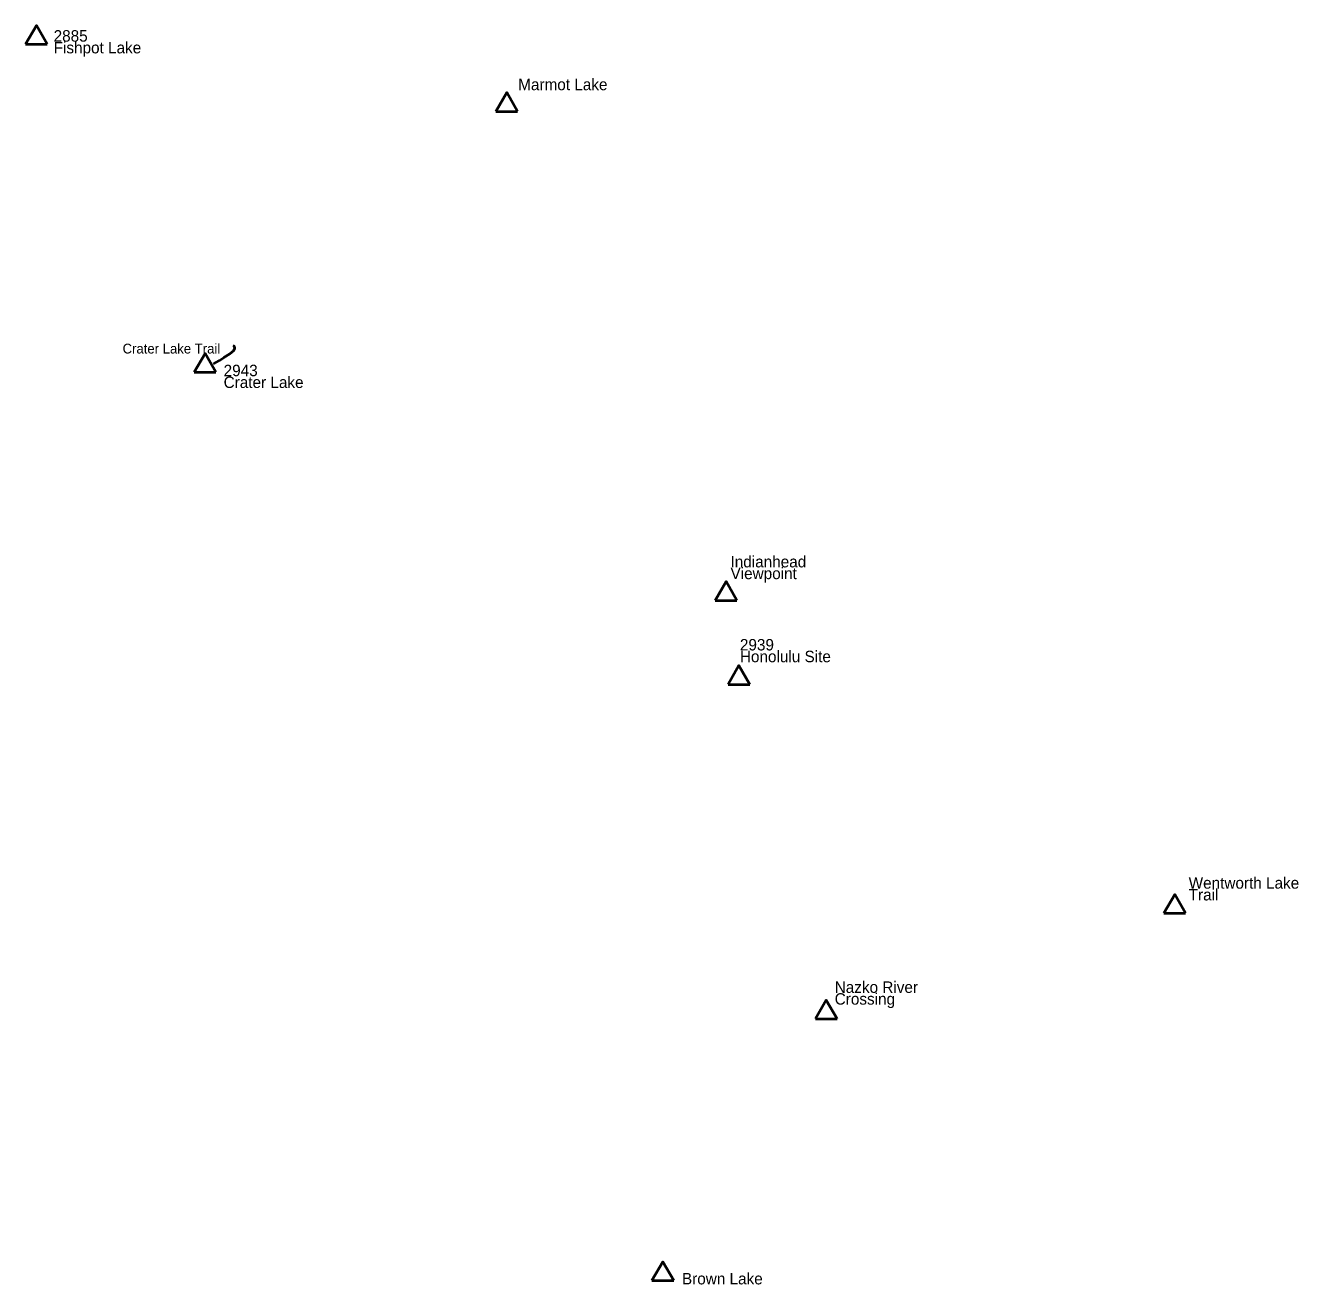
# Model space of a CAD drawing. Extents: x 322505 to 642419, y 5806860 to 5919753.
# Drawn here: x 446984 to 485932, y 5828406 to 5866932 of the extents above; entities that cross this region are included whole.
import ezdxf

# ---------------------------------------------------------------- set-up
doc = ezdxf.new("R2010")
doc.units = 0
doc.header["$LTSCALE"] = 140
for name, color, linetype, lineweight in [('1', 7, 'Continuous', 40), ('2', 7, 'Continuous', 40), ('4', 7, 'Continuous', 40)]:
    doc.layers.add(name, color=color, linetype=linetype, lineweight=lineweight)

msp = doc.modelspace()

# ---------------------------------------------------------------- linework, layer by layer
at = {"layer": '1'}
for p, q in [((446984.4, 5866355.9), (447649.8, 5866355.9)), ((452147.8, 5856320.9), (452813.2, 5856320.9)), ((468478.9, 5846770.9), (469144.3, 5846770.9))]:
    msp.add_line(p, q, dxfattribs=at)
for points in [[(447649.8, 5866355.9), (447317.1, 5866932.1), (446984.4, 5866355.9)], [(452813.2, 5856320.9), (452480.5, 5856897.1), (452147.8, 5856320.9)], [(469144.3, 5846770.9), (468811.6, 5847347.1), (468478.9, 5846770.9)]]:
    msp.add_lwpolyline(points, dxfattribs=at)
at = {"layer": '2'}
for p, q in [((461375.5, 5864300.4), (462040.8, 5864300.4)), ((468085.1, 5849337.4), (468750.5, 5849337.4)), ((481813.1, 5839766.9), (482478.5, 5839766.9)), ((471151.8, 5836535.9), (471817.2, 5836535.9)), ((466150.4, 5828529.4), (466815.8, 5828529.4))]:
    msp.add_line(p, q, dxfattribs=at)
for points in [[(462040.8, 5864300.4), (461708.2, 5864876.6), (461375.5, 5864300.4)], [(468750.5, 5849337.4), (468417.8, 5849913.6), (468085.1, 5849337.4)], [(482478.5, 5839766.9), (482145.8, 5840343.1), (481813.1, 5839766.9)], [(471817.2, 5836535.9), (471484.5, 5837112.1), (471151.8, 5836535.9)], [(466815.8, 5828529.4), (466483.1, 5829105.6), (466150.4, 5828529.4)]]:
    msp.add_lwpolyline(points, dxfattribs=at)
at = {"layer": '4'}
msp.add_lwpolyline([(452741, 5856583), (452922.7, 5856684.1), (453057.6, 5856775), (453234.7, 5856881.8), (453361.2, 5856988.6), (453390.7, 5857059.7), (453378.1, 5857107.2), (453335.9, 5857138.8)], dxfattribs=at)

# ---------------------------------------------------------------- texts
at = {"layer": '1'}
for s, p in [('2885', (447846.6, 5866438.1)), ('Fishpot Lake', (447846.6, 5866078.1)), ('2943', (453047.5, 5856200.1)), ('Crater Lake', (453047.5, 5855840.1)), ('2939', (468841.8, 5847808.3)), ('Honolulu Site', (468841.8, 5847448.3))]:
    msp.add_text(s, height=350, dxfattribs=at).set_placement(p)
at = {"layer": '2'}
for s, p in [('Marmot Lake', (462059.1, 5864951.2)), ('Indianhead', (468554.2, 5850349.9)), ('Viewpoint', (468554.2, 5849989.9)), ('Wentworth Lake', (482571, 5840519.3)), ('Trail', (482571, 5840159.3)), ('Nazko River', (471741.9, 5837330.6)), ('Crossing', (471741.9, 5836970.6)), ('Brown Lake', (467068.3, 5828410.9))]:
    msp.add_text(s, height=350, dxfattribs=at).set_placement(p)
at = {"layer": '4'}
msp.add_text('Crater Lake Trail', height=300, dxfattribs=at).set_placement((449956.2, 5856894.1))

doc.saveas('drawing.dxf')
